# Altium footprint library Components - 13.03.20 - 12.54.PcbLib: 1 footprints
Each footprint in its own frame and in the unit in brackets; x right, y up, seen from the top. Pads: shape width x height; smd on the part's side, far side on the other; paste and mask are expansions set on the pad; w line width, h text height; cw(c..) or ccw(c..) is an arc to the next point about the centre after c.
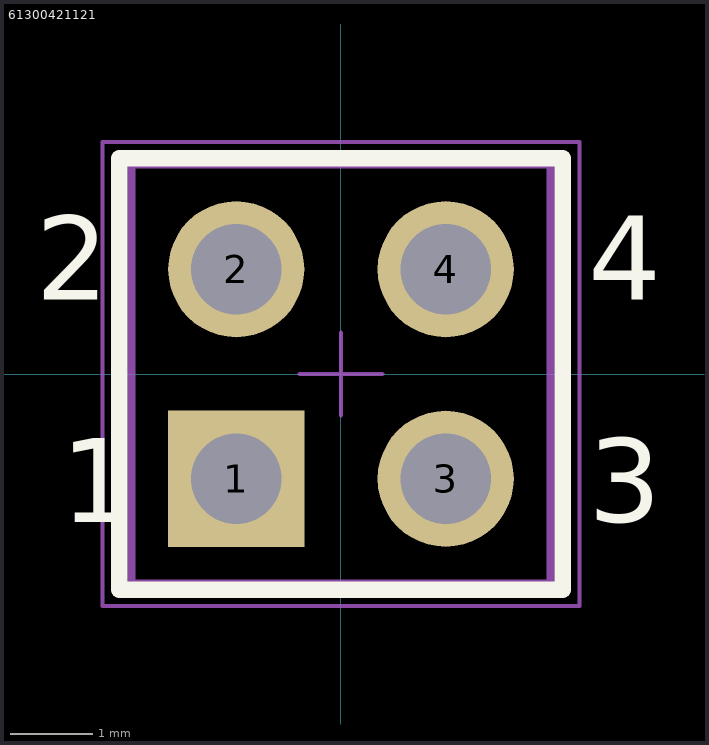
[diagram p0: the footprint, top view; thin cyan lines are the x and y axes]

## 61300421121 [mm] "Pin Header, pitch 2.54 mm, THT, Vertical, dual row, 4p"
height 8.54
pads (4):
  rect 1.65x1.65 hole 1.1: 1(-1.27,-1.27)
  round 1.65 hole 1.1: 2(-1.27,1.27) 3(1.27,-1.27) 4(1.27,1.27)
Top Overlay:
  lines w0.2: -2.69,-2.615 2.69,-2.615 2.69,2.615 -2.69,2.615 -2.69,-2.615
  text "4" at 3,0.9 h1.02
  text "3" at 3,-1.8 h1.02
  text "2" at -3.7,0.9 h1.02
  text "1" at -3.4,-1.8 h1.02
Mechanical 13:
  lines w0.1: -2.54,-2.54 2.54,-2.54 2.54,2.54 -2.54,2.54 -2.54,-2.54
Mechanical 15:
  lines w0.05: -0.5,0 0.5,0 ; 0,-0.5 0,0.5 ; -2.89,-2.815 -2.89,2.815 2.89,2.815 2.89,-2.815 -2.89,-2.815
3D body "61300421121.stp": height 8.59, standoff -2.95, extent -2.54,-2.54 2.54,2.54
